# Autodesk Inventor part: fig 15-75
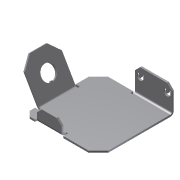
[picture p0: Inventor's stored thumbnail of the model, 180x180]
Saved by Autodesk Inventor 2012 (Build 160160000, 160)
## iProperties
Shininess: 77.0
Angle Display Precision: 2
Document Length Units: 11269
Document Angle Units: 11279
Document Time Units: 11290
Document Mass Units: 11283
Document Length Units Precision: 3
Document Angle Units Precision: 2
Created: 2002-04
Part Number: fig 15-75
Document SubType Name: Sheet Metal
Density: 1 g/cm^3
Sheet Metal Rule: Default
Material: Default
Density: 0.0
Volumn: 0.0
Area: 0.0
PropertySet Name: Model Information
Control State: 0
Master: False
Checked Out: False
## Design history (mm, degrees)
node "Face1"
  sketch "Sketch1"
    geometry: L1 (12.647, 25.882)-(12.647, -14.118); L2 (12.647, -14.118)-(-17.353, -14.118); L3 (-17.353, -14.118)-(-17.353, 15.882); L4 (-17.353, 15.882)-(-2.353, 15.882); L5 (-2.353, 15.882)-(-2.353, 25.882); L6 (-2.353, 25.882)-(12.647, 25.882); 1 further point
    constraints: 12 end point, 4 parallel, 1 perpendicular
    dimensions: "d5" = 30 distance of L2.end L3.end; "d6" = 10 distance of L4.end L5.end; "d7" = 15 distance of L3.end L4.end; "d25" = 15 distance of L5.end L1.start
sketch "Sketch3"
  geometry: L1 (10, -15)-(10, 0)
  constraints: 2 end point
feature "Fold3" sketch "Sketch3" dims "d26" = 0.75 (= BendRadius), "d27" = 90 deg, "d28" = 0.75 (= BendRadius), "d96" = 0.75 (= BendReliefWidth), "d97" = 0.375 (= BendReliefDepth), "d98" = 1.5 (= MinimumRemnant), "SeamGap" = 0.01, "Thickness" = 0.75
node "Flange2"
sketch "Sketch6"
  geometry: L1 (-6.914, 3.413)-(-5.843, 3.413); L2 (-5.843, 0.624)-(-6.914, 0.624); L3 (-6.914, 2.432)-(-5.843, 2.432); L4 (-5.843, 1.605)-(-6.914, 1.605); L5 (-6.914, 0.624)-(-6.914, 1.605); L6 (-6.914, 2.432)-(-6.914, 3.413); L7 (-6.914, 12.568)-(-6.914, 11.587); L8 (-6.914, 14.376)-(-6.914, 13.395); L9 (-6.914, 11.587)-(-5.843, 11.587); L10 (-5.843, 14.376)-(-6.914, 14.376); L11 (-6.914, 12.568)-(-5.843, 12.568); L12 (-5.843, 13.395)-(-6.914, 13.395); A1 r 1.394 centre (-5.843, 2.018) between (-5.843, 0.624) and (-5.843, 3.413); A2 r 0.413 centre (-5.843, 2.018) between (-5.843, 1.605) and (-5.843, 2.432); A3 r 1.394 centre (-5.843, 12.982) between (-5.843, 11.587) and (-5.843, 14.376); A4 r 0.413 centre (-5.843, 12.982) between (-5.843, 12.568) and (-5.843, 13.395)
  constraints: 24 end point, 8 point on circle, 4 centre point, 3 equal length, 1 perpendicular
cut "Cut1" sketch "Sketch6" dims "d49" = 0.75 (= Thickness), "d50" = 0
node "Flange3"
feature "Corner Chamfer1" dims "d70" = 4, "d71" = 4, angle "d105" = 45 deg
feature "Corner Chamfer2" dims "d72" = 2, "d73" = 2, angle "d106" = 45 deg
sketch "Sketch10"
  geometry: 1 further point
feature "iFeature15:3" sketch "Sketch10"
body "Solid1"
face "Plate1" dims "Thickness" = 0.75
sketch "Sketch5"
  geometry: L1 (20, 0)-(5, 0); L2 (5, 0)-(5, 15); L3 (5, 15)-(20, 15); L4 (20, 15)-(20, 0)
  constraints: 8 end point
face "Plate6" dims "d35" = 10, "d36" = 5, "d38" = 15, "d39" = 60 deg, "d40" = 0.75 (= BendRadius), "Thickness" = 0.75, "MinimumRemnant" = 1.5 (= 2 x Thickness), "BendReliefWidth" = 0.75 (= Thickness)
bend "Bend5" dims "d38" = 15, "d39" = 60 deg, "d40" = 0.75 (= BendRadius), "d99" = 0.75 (= BendReliefWidth), "d100" = 0.375 (= BendReliefDepth), "d101" = 1.5 (= MinimumRemnant), "SeamGap" = 0.01, "Thickness" = 0.75, "MinimumRemnant" = 1.5 (= 2 x Thickness), "BendReliefWidth" = 0.75 (= Thickness), "TransitionRadius" = 0.75 (= BendRadius)
sketch "Sketch7"
  geometry: L1 (25, 0)-(15, 0); L2 (15, 0)-(15, 5); L3 (15, 5)-(25, 5); L4 (25, 5)-(25, 0)
  constraints: 8 end point
face "Plate7" dims "d57" = 5, "d58" = 10, "d60" = 5, "d61" = 90 deg, "d62" = 0.75 (= BendRadius), "Thickness" = 0.75, "MinimumRemnant" = 1.5 (= 2 x Thickness), "BendReliefWidth" = 0.75 (= Thickness)
bend "Bend7" dims "d59" = 0.75 (= BendRadius), "d60" = 5, "d61" = 90 deg, "d62" = 0.75 (= BendRadius), "d102" = 0.75 (= BendReliefWidth), "d103" = 0.375 (= BendReliefDepth), "d104" = 1.5 (= MinimumRemnant), "SeamGap" = 0.01, "Thickness" = 0.75, "MinimumRemnant" = 1.5 (= 2 x Thickness), "BendReliefWidth" = 0.75 (= Thickness)
other parameters: "BendRadius" = 0.75 (= Thickness), "BendReliefDepth" = 0.375 (= 0.5 x Thickness), "CornerReliefSize" = 3 (= 4 x Thickness), "d0" = 0.75 (= BendRadius), "d13" = 0.75 (= BendRadius), "d31" = 0.75 (= BendRadius), "d37" = 0.75 (= BendRadius), "d112" = 0, "JacobiRadiusSize" = 0.75 (= Thickness), "GapSize" = 0.75 (= Thickness)
